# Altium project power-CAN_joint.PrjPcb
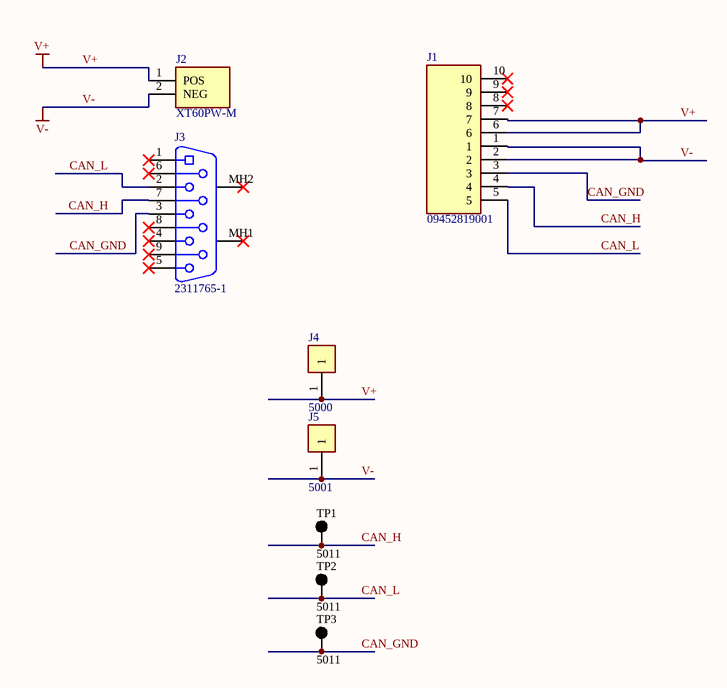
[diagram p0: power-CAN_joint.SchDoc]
1 sheet, 8 parts. Net scope: global (net labels, ports and power ports of the same name join across sheets).
Board file: power-CAN_joint.PcbDoc

## Sheet power-CAN_joint.SchDoc
size A3; SheetNumber: 1; SheetTotal: 1

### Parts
J1  09452819001  [09452812561]
J2  XT60PW-M  [AMASS_XT60PW-M]
J3  2311765-1  [TECO-2311765-1_V]
J4  5000  [FP-5000-MFG]
J5  5001  [FP-5001-MFG]
TP1  5011  [KSTN-5011_V]
TP2  5011  [KSTN-5011_V]
TP3  5011  [KSTN-5011_V]

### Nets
V+: J1.6 J1.7 J2.1(POS) J4.1
V-: J1.1 J1.2 J2.2(NEG) J5.1
CAN_GND: J1.3 J3.3 TP3.1
CAN_H: J1.4 J3.7 TP1.1
CAN_L: J1.5 J3.2 TP2.1

Not connected (* = marked no-connect by the designer): J1 8* 9* 10*; J3 1* 4* 5* 6* 8* 9* MH1* MH2*

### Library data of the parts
J1 = 09452819001: Connector; Manufacturer_Name: HARTING
J2 = CMP-002-000000-1: Socket, DC supply, male, PIN: 2; MF: AMASS
J3 = CMP-2000-07623-1: D-Sub Receptacle, Pitch 2.77 mm, 1 x 9 Position, Height 12.55 mm, -55 to 105 degC, RoHS; Manufacturer: TEConnectivity
J4 = CMP-19636-000027-1: PC TEST POINT MINIATURE RED; Outside Diameter: 2.54mm; Body Material: Bronze; Number of Contacts: 1; Insulation: Insulated; Inside Diameter: 1.27mm; Hole Diameter: 1.6mm; Plating: Silver
J5 = CMP-2000-05181-2: PC TEST POINT MINIATURE BLACK; Body Material: Bronze; Plating: Silver; Inside Diameter: 1.27mm; Hole Diameter: 1.6mm; Number of Ports: 1; Outside Diameter: 2.54mm; Insulation: Insulated
TP1-TP3 = CMP-1672-00003-4: Test Point, Black, Through Hole, RoHS, Bulk; Manufacturer: Keystone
